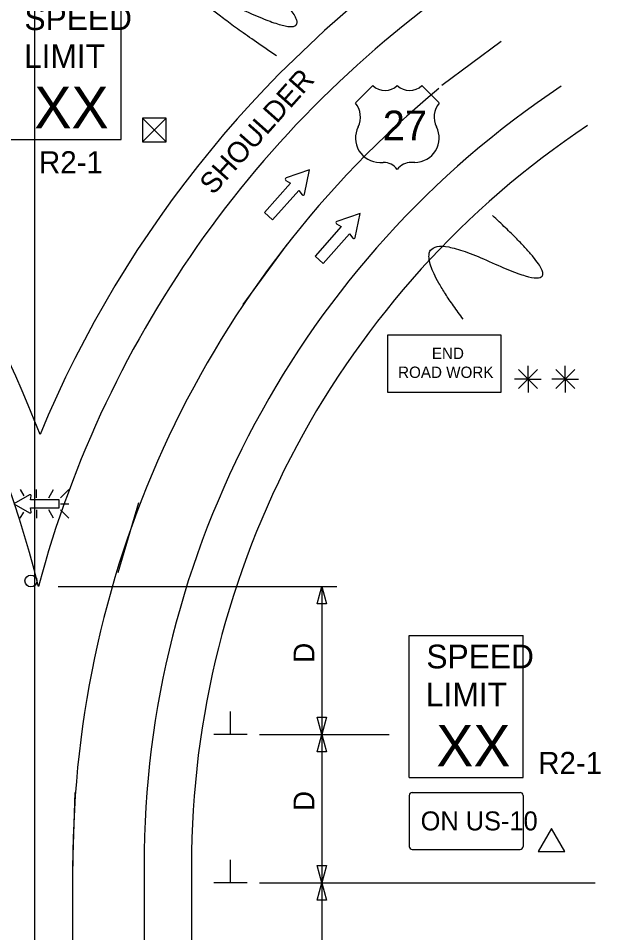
# Model space of a CAD drawing. Extents: x 16303 to 18479, y 5704 to 6974.
# Drawn here: x 16999.2 to 17195.7, y 6502.5 to 6811 of the extents above; entities that cross this region are included whole.
import ezdxf

# ---------------------------------------------------------------- set-up
doc = ezdxf.new("R2010")
doc.units = 0
for name, color, linetype in [('ALI_LEGAL_EX', 7, 'Continuous'), ('MT_SCRATCH_LEVEL_E', 7, 'Continuous'), ('PAVT_EDGE_EX', 7, 'Continuous'), ('TRAFFIC_SIGNS_PR', 7, 'Continuous'), ('TYPICAL_EX', 7, 'Continuous'), ('TYPICAL_TEXT_DIMEN_PR', 7, 'Continuous')]:
    doc.layers.add(name, color=color, linetype=linetype)

msp = doc.modelspace()

# ---------------------------------------------------------------- linework, layer by layer
at = {"layer": 'ALI_LEGAL_EX'}
for p, q in [((17004.68, 6974.12), (17004.68, 6155.98)), ((17004.68, 6877.04), (17004.68, 6013.12)), ((17039.84, 6647.53), (17032.85, 6623.88)), ((17017.65, 6024.8), (17017.65, 6525.15))]:
    msp.add_line(p, q, dxfattribs=at)
for points in [[(17142.04, 6788.34), (17162.08, 6803.27)], [(17075.14, 6714.42), (17089.89, 6734.61)], [(17017.7, 6524.8), (17017.65, 6525.15), (17018.48, 6549.78)]]:
    msp.add_lwpolyline(points, dxfattribs=at)
msp.add_arc((17357.65, 6525.15), 340, 129.5666, 180, dxfattribs=at)
at = {"layer": 'MT_SCRATCH_LEVEL_E'}
for p, q in [((17097.48, 6759.79), (17089.6, 6757.11)), ((17095.77, 6751.62), (17097.48, 6759.79)), ((17091.04, 6755.33), (17082.24, 6745.42)), ((17089.5, 6756.28), (17091.04, 6755.33)), ((17085.03, 6742.93), (17093.84, 6752.84)), ((17093.84, 6752.84), (17094.96, 6751.43)), ((17082.24, 6745.42), (17085.03, 6742.93)), ((17114.56, 6745.13), (17106.68, 6742.45)), ((17112.85, 6736.96), (17114.56, 6745.13)), ((17108.12, 6740.67), (17099.32, 6730.76)), ((17106.59, 6741.62), (17108.12, 6740.67)), ((17102.12, 6728.28), (17110.92, 6738.19)), ((17110.92, 6738.19), (17112.04, 6736.77)), ((17099.32, 6730.76), (17102.12, 6728.28))]:
    msp.add_line(p, q, dxfattribs=at)
for centre, start, end in [((17089.75, 6756.67), 108.8028, 238.3418), ((17095.31, 6751.73), 218.4141, 348.1511), ((17106.84, 6742.01), 108.8028, 238.3418), ((17112.4, 6737.07), 218.4141, 348.1511)]:
    msp.add_arc(centre, 0.463, start, end, dxfattribs=at)
at = {"layer": 'PAVT_EDGE_EX'}
for p, q in [((17041.65, 6525.15), (17041.65, 6062.71)), ((17057.65, 6525.15), (17057.65, 6062.71))]:
    msp.add_line(p, q, dxfattribs=at)
for centre, radius, start, end in [((16629.65, 6525.15), 404, 21.0961, 68.7791), ((16629.65, 6525.15), 388, 14.0482, 68.7791), ((17357.65, 6525.15), 380, 123.6935, 157.5011), ((17357.65, 6525.15), 364, 123.6935, 165.0045), ((17357.65, 6525.15), 316, 123.6935, 180), ((17357.65, 6525.15), 300, 123.6935, 180), ((17357.65, 6525.15), 300, 180, 180.00000277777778)]:
    msp.add_arc(centre, radius, start, end, dxfattribs=at)
at = {"layer": 'TRAFFIC_SIGNS_PR'}
for p, q in [((17033.95, 6770.12), (17033.95, 6818.12)), ((16995.55, 6770.12), (17033.95, 6770.12)), ((17001.2, 6649.83), (16999.94, 6652.01)), ((17005.38, 6649.19), (17005.38, 6652.01)), ((17009.51, 6649.19), (17011.14, 6652.01)), ((17013.47, 6649.19), (17016.29, 6652.02)), ((16999.91, 6642.31), (17001.12, 6644.4)), ((17005.38, 6645.13), (17005.38, 6642.31)), ((17011.17, 6642.31), (17009.54, 6645.13)), ((17013.47, 6647.16), (17016.29, 6647.16)), ((17013.47, 6645.13), (17016.29, 6642.31)), ((17131.11, 6602.81), (17169.51, 6602.81)), ((17131.11, 6554.81), (17131.11, 6602.81)), ((17169.51, 6554.81), (17169.51, 6602.81)), ((17131.11, 6554.81), (17169.51, 6554.81)), ((17131.11, 6548.81), (17131.11, 6531.61)), ((17132.11, 6549.81), (17168.51, 6549.81)), ((17169.51, 6548.81), (17169.51, 6531.61)), ((17132.11, 6530.61), (17168.51, 6530.61))]:
    msp.add_line(p, q, dxfattribs=at)
msp.add_lwpolyline([(17123.73, 6684.89), (17162.13, 6684.89), (17162.13, 6704.09), (17123.73, 6704.09)], close=True, dxfattribs=at)
for points in [[(17003.05, 6650.18), (16997.74, 6647.16), (17003.05, 6644.12)], [(17003.55, 6644.48), (17003.32, 6645.78), (17013.05, 6645.78), (17013.05, 6648.52), (17003.32, 6648.52), (17003.56, 6649.82)]]:
    msp.add_lwpolyline(points, dxfattribs=at)
msp.add_circle((17003.5, 6621.15), 2, dxfattribs=at)
for centre, radius, start, end in [((17003.22, 6649.88), 0.341, 350.7308, 118.8916), ((17003.22, 6644.42), 0.341, 241.4833, 9.9593), ((17132.11, 6548.81), 1, 90, 180), ((17168.51, 6548.81), 1, 0, 90), ((17132.11, 6531.61), 1, 180, 270), ((17168.51, 6531.61), 1, 270, 0)]:
    msp.add_arc(centre, radius, start, end, dxfattribs=at)
at = {"layer": 'TYPICAL_EX'}
for p, q in [((17112.93, 6782.38), (17118.83, 6788.28)), ((17141.23, 6782.38), (17135.33, 6788.28)), ((17121.17, 6762.32), (17122.35, 6762.32)), ((17132.98, 6762.32), (17131.8, 6762.32))]:
    msp.add_line(p, q, dxfattribs=at)
for centre, radius, start, end in [((17122.95, 6792.57), 5.96, 226.1404, 313.8596), ((17131.21, 6792.57), 5.96, 226.1404, 313.8596), ((17107.34, 6777.66), 7.31, 333.0977, 40.1936), ((17146.82, 6777.66), 7.31, 139.8064, 206.9023), ((17121.19, 6770.57), 8.24, 152.6698, 269.9013), ((17132.97, 6770.57), 8.24, 270.0987, 27.3302), ((17122.37, 6756.42), 5.91, 37.1038, 90.1385), ((17131.79, 6756.42), 5.91, 89.8615, 142.8962)]:
    msp.add_arc(centre, radius, start, end, dxfattribs=at)
at = {"layer": 'TYPICAL_TEXT_DIMEN_PR'}
for p, q in [((17041.08, 6777.24), (17049.08, 6769.24)), ((17041.08, 6769.24), (17049.08, 6777.24)), ((17171.16, 6689.26), (17171.16, 6693.72)), ((17183.71, 6689.26), (17183.71, 6693.72)), ((17167.97, 6692.45), (17174.34, 6686.07)), ((17174.34, 6692.45), (17167.97, 6686.07)), ((17186.9, 6692.45), (17180.52, 6686.07)), ((17180.53, 6692.45), (17186.9, 6686.07)), ((17171.16, 6689.26), (17166.62, 6689.26)), ((17171.16, 6689.26), (17174.34, 6689.26)), ((17171.16, 6689.26), (17175.63, 6689.26)), ((17171.16, 6689.26), (17171.16, 6684.76)), ((17183.71, 6689.26), (17179.18, 6689.26)), ((17183.71, 6689.26), (17186.9, 6689.26)), ((17183.71, 6689.26), (17188.19, 6689.26)), ((17183.71, 6689.26), (17183.71, 6684.76)), ((17012.72, 6619.33), (17106.65, 6619.33)), ((17100.08, 6613.47), (17101.65, 6619.33)), ((17101.65, 6619.33), (17101.65, 6569.33)), ((17101.65, 6619.33), (17103.22, 6613.47)), ((17101.65, 6613.47), (17100.08, 6613.47)), ((17103.22, 6613.47), (17101.65, 6613.47)), ((17070.77, 6569.33), (17070.77, 6577.11)), ((17101.65, 6569.33), (17100.08, 6575.19)), ((17100.08, 6575.19), (17101.65, 6575.19)), ((17101.65, 6575.19), (17103.22, 6575.19)), ((17103.22, 6575.19), (17101.65, 6569.33)), ((17076.4, 6569.33), (17065.15, 6569.33)), ((17080.65, 6569.33), (17124.34, 6569.33)), ((17100.08, 6563.47), (17101.65, 6569.33)), ((17101.65, 6569.33), (17101.65, 6519.33)), ((17101.65, 6569.33), (17103.22, 6563.47)), ((17101.65, 6563.47), (17100.08, 6563.47)), ((17103.22, 6563.47), (17101.65, 6563.47)), ((17070.77, 6519.33), (17070.77, 6527.11)), ((17101.65, 6519.33), (17100.08, 6525.19)), ((17100.08, 6525.19), (17101.65, 6525.19)), ((17101.65, 6525.19), (17103.22, 6525.19)), ((17103.22, 6525.19), (17101.65, 6519.33)), ((17076.4, 6519.33), (17065.15, 6519.33)), ((17080.65, 6519.33), (17193.84, 6519.33)), ((17100.08, 6513.47), (17101.65, 6519.33)), ((17101.65, 6519.33), (17103.22, 6513.47)), ((17101.65, 6519.33), (17101.65, 6469.33)), ((17101.65, 6513.47), (17100.08, 6513.47)), ((17103.22, 6513.47), (17101.65, 6513.47))]:
    msp.add_line(p, q, dxfattribs=at)
for points in [[(17041.08, 6777.24), (17041.08, 6769.24), (17049.08, 6769.24), (17049.08, 6777.24)], [(17179.06, 6537.67), (17174.54, 6529.84), (17183.59, 6529.84)]]:
    msp.add_lwpolyline(points, close=True, dxfattribs=at)
for points in [[(17086.35, 6798.24), (17039.53, 6830.07), (17110.85, 6797.33), (17076.24, 6829.21)], [(17149.31, 6709.45), (17122.41, 6745.3), (17193.74, 6712.56), (17159.13, 6744.44)]]:
    msp.add_open_spline(points, degree=2, dxfattribs=at)

# ---------------------------------------------------------------- texts
at = {"layer": 'TRAFFIC_SIGNS_PR'}
for s, height, p in [('SPEED', 8, (17001.31, 6806.98)), ('LIMIT', 8, (17001.15, 6794.18)), ('XX', 14.031, (17004.66, 6773.88)), ('R2-1', 7.44, (17006.22, 6758.68)), ('END', 3.831, (17138.73, 6696.02)), ('ROAD WORK', 3.831, (17127.34, 6689.63)), ('SPEED', 8, (17136.88, 6591.67)), ('LIMIT', 8, (17136.72, 6578.87)), ('XX', 14.031, (17140.22, 6558.57)), ('R2-1', 7.44, (17174.6, 6556.06)), ('ON US-10', 6.4, (17134.95, 6537.01))]:
    msp.add_text(s, height=height, dxfattribs=at).set_placement(p)
at = {"layer": 'TYPICAL_EX'}
msp.add_text('27', height=10, dxfattribs=at).set_placement((17122.19, 6769.81))
at = {"layer": 'TYPICAL_TEXT_DIMEN_PR'}
for s, rotation, p in [('SHOULDER', 48.378, (17065, 6751.09)), ('D', 90, (17099.09, 6593.55)), ('D', 90, (17099.09, 6543.55))]:
    msp.add_text(s, height=7, rotation=rotation, dxfattribs=at).set_placement(p)

doc.saveas('drawing.dxf')
